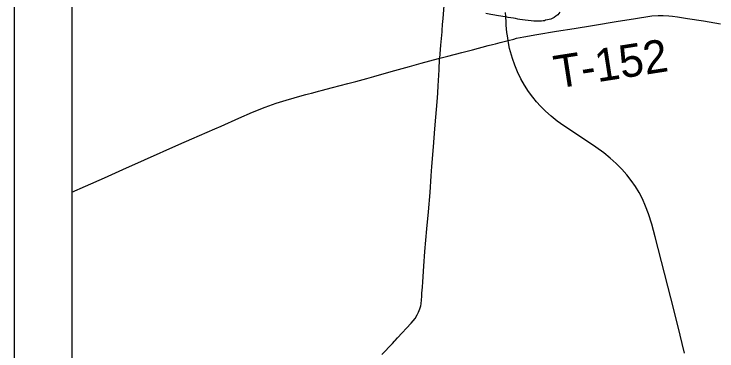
# Model space of a CAD drawing. Extents: x -19.5 to 44.1, y 0 to 22.
# Drawn here: x -19.48 to -18.261, y 6.796 to 7.38 of the extents above; entities that cross this region are included whole.
import ezdxf

# ---------------------------------------------------------------- set-up
doc = ezdxf.new("R2010")
doc.units = 0
for name, color, linetype in [('GM_X_County_Road', 7, 'Continuous'), ('GM_X_Major_River', 7, 'Continuous'), ('GM_X_State_Route', 7, 'Continuous'), ('GM_X_Township_Road', 7, 'Continuous'), ('GM_X_Township_Road_Text', 7, 'Continuous'), ('SH_Data', 7, 'Continuous')]:
    doc.layers.add(name, color=color, linetype=linetype)

msp = doc.modelspace()

# ---------------------------------------------------------------- linework, layer by layer
at = {"layer": 'GM_X_County_Road'}
for points in [[(-18.7419, 7.3037), (-18.7401, 7.3263), (-18.7379, 7.3497), (-18.7376, 7.3551), (-18.7373, 7.3586), (-18.737, 7.362), (-18.7365, 7.3674), (-18.736, 7.3728), (-18.7342, 7.395), (-18.7322, 7.4192), (-18.7312, 7.4329), (-18.731, 7.4362), (-18.7301, 7.448)], [(-18.7419, 7.3037), (-18.7276, 7.3075), (-18.7035, 7.3137), (-18.6853, 7.3184), (-18.6581, 7.3257), (-18.6503, 7.3276), (-18.6449, 7.3289), (-18.6372, 7.331), (-18.6326, 7.3322), (-18.6233, 7.3345)], [(-19.38, 7.0712), (-19.3559, 7.0818), (-19.323, 7.0964), (-19.2912, 7.1106), (-19.2537, 7.1273), (-19.1943, 7.1543), (-19.1717, 7.1641), (-19.132, 7.1813), (-19.121, 7.186), (-19.0902, 7.1999), (-19.0663, 7.2101), (-19.0444, 7.2189), (-19.0257, 7.2255), (-19.0079, 7.2311), (-18.9804, 7.2388), (-18.9739, 7.2406), (-18.9697, 7.2417), (-18.9643, 7.2431), (-18.9577, 7.2449), (-18.9518, 7.2464), (-18.9476, 7.2475), (-18.9278, 7.2528), (-18.9014, 7.2598), (-18.8876, 7.2635), (-18.8684, 7.2687), (-18.8559, 7.2722), (-18.8259, 7.2807), (-18.7944, 7.2894), (-18.7743, 7.2951), (-18.7438, 7.3032), (-18.7419, 7.3037)], [(-18.8422, 6.7899), (-18.824, 6.8091), (-18.8202, 6.8131), (-18.8193, 6.814), (-18.815, 6.8184), (-18.7915, 6.8441), (-18.7847, 6.8522), (-18.7807, 6.8586), (-18.7784, 6.8631), (-18.7761, 6.869), (-18.7748, 6.8739), (-18.7742, 6.8776), (-18.7735, 6.8844), (-18.773, 6.8906), (-18.7726, 6.8962), (-18.7723, 6.9016), (-18.772, 6.9067), (-18.7713, 6.9159), (-18.7693, 6.9427), (-18.7674, 6.9685), (-18.764, 7.0075), (-18.7614, 7.0371), (-18.7587, 7.0706), (-18.7566, 7.0997), (-18.7553, 7.1158), (-18.7528, 7.1498), (-18.7503, 7.1814), (-18.7459, 7.2352), (-18.7453, 7.2439), (-18.7445, 7.2557), (-18.7428, 7.2836), (-18.742, 7.3025), (-18.7419, 7.3037)]]:
    msp.add_lwpolyline(points, dxfattribs=at)
at = {"layer": 'GM_X_Major_River'}
msp.add_lwpolyline([(-18.5338, 7.3835), (-18.5373, 7.379), (-18.5403, 7.3768), (-18.5434, 7.3745), (-18.5491, 7.3716), (-18.5548, 7.3701), (-18.5583, 7.3694), (-18.5602, 7.3687), (-18.5624, 7.3683), (-18.5651, 7.368), (-18.5685, 7.3677), (-18.5723, 7.3677), (-18.5784, 7.3678), (-18.5833, 7.3683), (-18.5883, 7.3691), (-18.5936, 7.3699), (-18.5985, 7.3704), (-18.6027, 7.3708), (-18.6064, 7.3716), (-18.6102, 7.3724), (-18.614, 7.3733), (-18.6186, 7.3737), (-18.6231, 7.3745), (-18.6273, 7.3757), (-18.6322, 7.3762), (-18.636, 7.3766), (-18.6398, 7.3771), (-18.6432, 7.3779), (-18.6462, 7.3783), (-18.6496, 7.3787), (-18.653, 7.3795), (-18.6621, 7.3812)], dxfattribs=at)
at = {"layer": 'GM_X_State_Route'}
msp.add_lwpolyline([(-18.3173, 6.7921), (-18.3292, 6.8403), (-18.341, 6.8879), (-18.368, 6.9939), (-18.3743, 7.016), (-18.3799, 7.0337), (-18.3848, 7.0471), (-18.3903, 7.0595), (-18.396, 7.0705), (-18.4024, 7.0811), (-18.4097, 7.0918), (-18.4174, 7.1015), (-18.426, 7.1112), (-18.436, 7.1213), (-18.4462, 7.1304), (-18.4573, 7.1394), (-18.4712, 7.1496), (-18.4908, 7.1629), (-18.5266, 7.1864), (-18.5383, 7.1947), (-18.5485, 7.2029), (-18.5583, 7.2116), (-18.5672, 7.2204), (-18.5743, 7.2283), (-18.5806, 7.236), (-18.5878, 7.2462), (-18.5949, 7.2572), (-18.601, 7.2681), (-18.6067, 7.2799), (-18.6115, 7.2914), (-18.6156, 7.3032), (-18.6174, 7.3087), (-18.6206, 7.3205), (-18.622, 7.327), (-18.6233, 7.3345), (-18.6244, 7.3425), (-18.6252, 7.348), (-18.6259, 7.3546), (-18.6264, 7.3612), (-18.6268, 7.3661), (-18.6273, 7.376), (-18.6277, 7.3828)], dxfattribs=at)
at = {"layer": 'GM_X_Township_Road'}
msp.add_lwpolyline([(-18.6233, 7.3345), (-18.6134, 7.337), (-18.6086, 7.3382), (-18.5958, 7.3408), (-18.5734, 7.3448), (-18.5395, 7.3505), (-18.5088, 7.3555), (-18.4769, 7.3604), (-18.4326, 7.3677), (-18.406, 7.372), (-18.3738, 7.3769), (-18.3632, 7.3779), (-18.3544, 7.3778), (-18.3447, 7.3773), (-18.3383, 7.3766), (-18.3294, 7.3754), (-18.3119, 7.3728), (-18.2847, 7.3687), (-18.2547, 7.3634)], dxfattribs=at)
at = {"layer": 'SH_Data'}
for p, q in [((-19.48, 9.4611), (-19.48, 2.4611)), ((-19.38, 8.3173), (-19.38, 2.5611))]:
    msp.add_line(p, q, dxfattribs=at)

# ---------------------------------------------------------------- texts
at = {"layer": 'GM_X_Township_Road_Text'}
msp.add_text('T-152', height=0.05682, rotation=8.8708, dxfattribs=at).set_placement((-18.5391, 7.251))

doc.saveas('drawing.dxf')
